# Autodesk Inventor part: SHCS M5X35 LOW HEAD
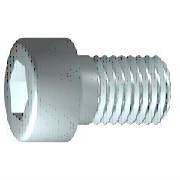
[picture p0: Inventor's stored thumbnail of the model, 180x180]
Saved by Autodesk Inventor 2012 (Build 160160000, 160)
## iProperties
Created: 2006-02
Part Number: SHCS M5X35 LOW HEAD
Material: Steel, Mild
Description: M5 x 30 SHCS
Document SubType Name: Modeling
Standard: DIN 7984
Designer: Andy Moles
Standards Organization: DIN
Language: en-US
Size Designation: M5 x 30
Categories: <MemberInstance><Categories><Category DisplayName="Fasteners" InternalName="e4da775c-781d-43d5-af7c-5136215cf5a6" Mnemonic="FSTN"><Category DisplayName="Bolts"
Density: 7.86 g/cm^3
Mass: 5.97669 g
Surface Area: 6.97701 cm^2
Volume: 0.760393 cm^3
Vendor: S
Author: Andy Moles
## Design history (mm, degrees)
workplane "Work Plane1"
revolve "Body" stored, may be unused: angle "d10" = 90 deg
sketch "Sketch2"
  geometry: L1 (0, -5.95)-(0, 5.95) reference; L2 (-5.95, 0)-(5.95, 0) reference; L3 (1.732, 0)-(0.866, -1.5); L4 (0.866, -1.5)-(-0.866, -1.5); L5 (-0.866, -1.5)-(-1.732, 0); L6 (-1.732, 0)-(-0.866, 1.5); L7 (-0.866, 1.5)-(0.866, 1.5); L8 (0.866, 1.5)-(1.732, 0); 2 further points
  constraints: 12 end point, 1 coincident, 1 horizontal alignment, 1 point on line, 12 other
extrude "Slot" join sketch "Sketch2" stored distance "d11" = 10; taper "d12" = 0 deg
body "Solid1"
fillet "Fillet1" dims "d17" = 0.5 (= RR)
feature "Thread" dims "d13" = 30, "d14" = 0
chamfer "Chamfer1" distance "d15" = 0.49076 (= -0.5 x SPD + 0.5 x GD); stored, may be unused: second distance "d16" = 0.49076 (= GUL), angle "d27" = 45 deg
sketch "Sketch1"
  geometry: L1 (0.2, 0)-(35, 0); L2 (35, 0)-(35, 2.5); L3 (35, 2.5)-(19, 2.5); L4 (19, 2.5)-(18.509, 2.5); L5 (18.509, 2.5)-(0, 2.5); L6 (0, 2.5)-(0, 4.25); L7 (0, 4.25)-(-3.5, 4.25); L8 (-3.5, 4.25)-(-3.5, 1.732); L9 (-3.5, 1.732)-(-0.8, 1.732); L10 (-0.8, 1.732)-(0.2, 0); L11 (-10.2, 0)-(36.7, 0) reference; L12 (0, -0.85)-(0, 5.1) reference; L13 (19, 2.5)-(0, 2.5)
  constraints: 22 end point, 6 parallel, 2 collinear, 2 perpendicular, 1 horizontal, 1 point on line
  dimensions: "d1" = 16 distance from line of L3.end L2 (= GEL); "d2" = 0.49086 distance of L4.end L3.end (computed from GAL); "d3" = 3.5 distance between parallel lines of L8 L6 (= KOH); "d4" = 2.7 distance of L8.end L9.end (= INTI); "d5" = 60 deg angle of L10 L1; "d6" = 5 diameter of L3 L1 (= GD); "d7" = 5 diameter of L5 L1 (= BDM); "d8" = 3.4641 diameter of L9 L1 (= 1.1547 x SW); "d9" = 8.5 diameter of L7 L1 (= KOD); "d26" = 35 distance between parallel lines of L12 L2 (= NLG)
other parameters: "GD" = 5 (= NND) [user parameter; used in 2 equation terms], "NLG" = 35 [user parameter; used in 1 equation term], "GEL" = 16 [user parameter; used in 1 equation term], "KOD" = 8.5 [user parameter; used in 1 equation term], "KOH" = 3.5 [user parameter; used in 1 equation term], "INTI" = 2.7 [user parameter; used in 1 equation term], "GAL" = 0.49076 (= 0.61345 x PTC) [user parameter; used in 1 equation term], "GUL" = 0.49076 (= 0.61345 x PTC) [user parameter; used in 1 equation term], "BDM" = 5 (= NND) [user parameter; used in 1 equation term], "SW" = 3 [user parameter; used in 2 equation terms], "RR" = 0.5 [user parameter; used in 1 equation term], "SPD" = 4.01848 (= NND - 1.2269 x PTC) [user parameter; used in 1 equation term], "d19" = 0, "d28" = 0, "d29" = 0, "TOA" = 30 deg [user parameter], "GD1" = 4.01848 (= THREADDIA - 1.2269 x PTC) [user parameter], "THREADDIA" = 5 [user parameter; used in 1 equation term], "FAWI" = 45 deg [user parameter], "ANG" = 120 deg [user parameter], "TPU" = 12.5 (computed from PTC) [user parameter], "PTC" = 0.8 [user parameter; used in 5 equation terms], "NND" = 5 [user parameter; used in 3 equation terms], "E0" = 3.465 (= 1.155 x SW) [user parameter]
